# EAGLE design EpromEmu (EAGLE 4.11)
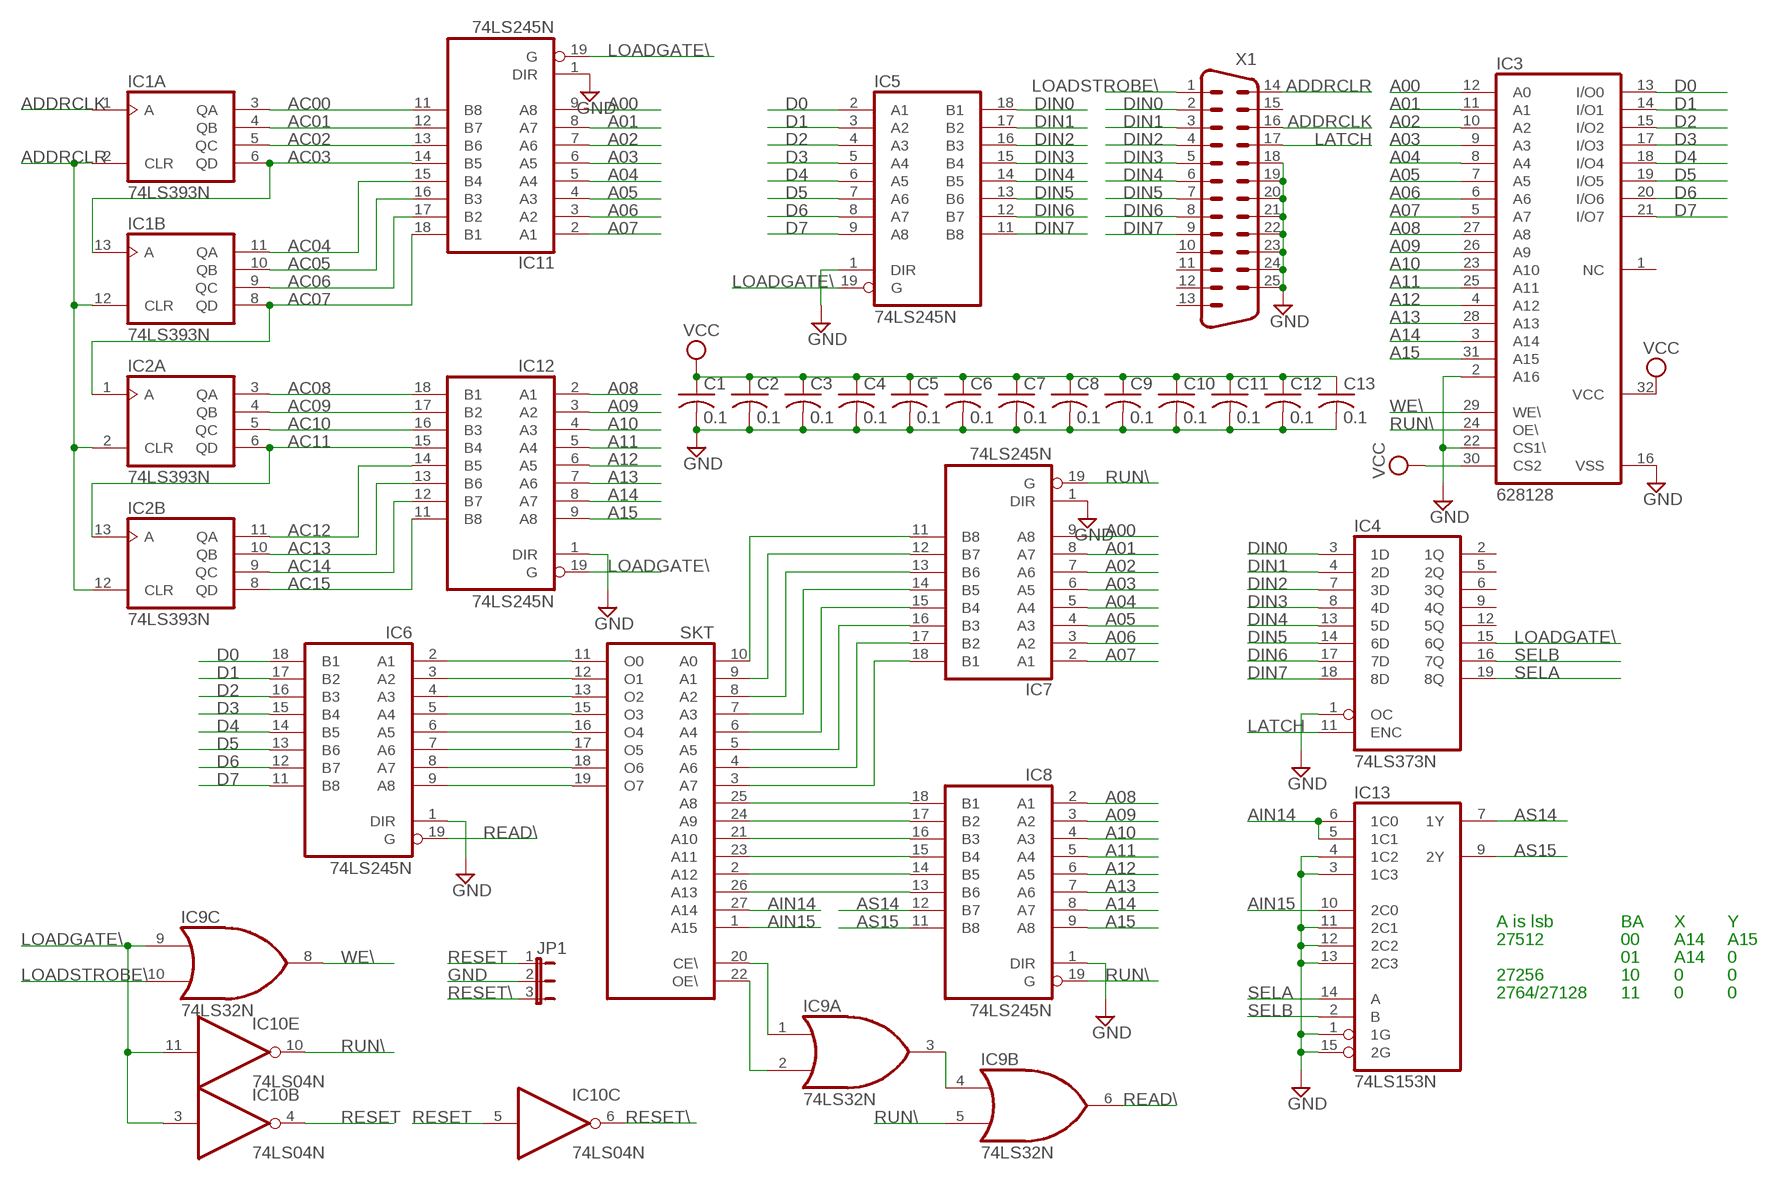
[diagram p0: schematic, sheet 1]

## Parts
C1  0.1  C-US050-025X075  [C050-025X075]
C2  0.1  C-US050-025X075  [C050-025X075]
C3  0.1  C-US050-025X075  [C050-025X075]
C4  0.1  C-US050-025X075  [C050-025X075]
C5  0.1  C-US050-025X075  [C050-025X075]
C6  0.1  C-US050-025X075  [C050-025X075]
C7  0.1  C-US050-025X075  [C050-025X075]
C8  0.1  C-US050-025X075  [C050-025X075]
C9  0.1  C-US050-025X075  [C050-025X075]
C10  0.1  C-US050-025X075  [C050-025X075]
C11  0.1  C-US050-025X075  [C050-025X075]
C12  0.1  C-US050-025X075  [C050-025X075]
C13  0.1  C-US050-025X075  [C050-025X075]
IC1  74LS393N  [DIL14]
IC2  74LS393N  [DIL14]
IC3  628128  628128P  [DIL32]
IC4  74LS373N  [DIL20]
IC5  74LS245N  [DIL20]
IC6  74LS245N  [DIL20]
IC7  74LS245N  [DIL20]
IC8  74LS245N  [DIL20]
IC9  74LS32N  [DIL14]
IC10  74LS04N  [DIL14]
IC11  74LS245N  [DIL20]
IC12  74LS245N  [DIL20]
IC13  74LS153N  [DIL16]
JP1  JP2E  [JP2]
SKT  27512  [DIL28]
X1  M25HP  [M25HP]

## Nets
A00: IC3.12(A0) IC7.9(A8) IC11.9(A8)
A01: IC3.11(A1) IC7.8(A7) IC11.8(A7)
A02: IC3.10(A2) IC7.7(A6) IC11.7(A6)
A03: IC3.9(A3) IC7.6(A5) IC11.6(A5)
A04: IC3.8(A4) IC7.5(A4) IC11.5(A4)
A05: IC3.7(A5) IC7.4(A3) IC11.4(A3)
A06: IC3.6(A6) IC7.3(A2) IC11.3(A2)
A07: IC3.5(A7) IC7.2(A1) IC11.2(A1)
A08: IC3.27(A8) IC8.2(A1) IC12.2(A1)
A09: IC3.26(A9) IC8.3(A2) IC12.3(A2)
A10: IC3.23(A10) IC8.4(A3) IC12.4(A3)
A11: IC3.25(A11) IC8.5(A4) IC12.5(A4)
A12: IC3.4(A12) IC8.6(A5) IC12.6(A5)
A13: IC3.28(A13) IC8.7(A6) IC12.7(A6)
A14: IC3.3(A14) IC8.8(A7) IC12.8(A7)
A15: IC3.31(A15) IC8.9(A8) IC12.9(A8)
AC00: IC1.3(A:QA) IC11.11(B8)
AC01: IC1.4(A:QB) IC11.12(B7)
AC02: IC1.5(A:QC) IC11.13(B6)
AC03: IC1.6(A:QD) IC1.13(B:A) IC11.14(B5)
AC04: IC1.11(B:QA) IC11.15(B4)
AC05: IC1.10(B:QB) IC11.16(B3)
AC06: IC1.9(B:QC) IC11.17(B2)
AC07: IC1.8(B:QD) IC2.1(A:A) IC11.18(B1)
AC08: IC2.3(A:QA) IC12.18(B1)
AC09: IC2.4(A:QB) IC12.17(B2)
AC10: IC2.5(A:QC) IC12.16(B3)
AC11: IC2.6(A:QD) IC2.13(B:A) IC12.15(B4)
AC12: IC2.11(B:QA) IC12.14(B5)
AC13: IC2.10(B:QB) IC12.13(B6)
AC14: IC2.9(B:QC) IC12.12(B7)
AC15: IC2.8(B:QD) IC12.11(B8)
ADDRCLK: IC1.1(A:A) X1.16
ADDRCLR: IC1.2(A:CLR) IC1.12(B:CLR) IC2.2(A:CLR) IC2.12(B:CLR) X1.14
AIN14: IC13.5(1C1) IC13.6(1C0) SKT.27(A14)
AIN15: IC13.10(2C0) SKT.1(A15)
AS14: IC8.12(B7) IC13.7(1Y)
AS15: IC8.11(B8) IC13.9(2Y)
D0: IC3.13(I/O0) IC5.2(A1) IC6.18(B1)
D1: IC3.14(I/O1) IC5.3(A2) IC6.17(B2)
D2: IC3.15(I/O2) IC5.4(A3) IC6.16(B3)
D3: IC3.17(I/O3) IC5.5(A4) IC6.15(B4)
D4: IC3.18(I/O4) IC5.6(A5) IC6.14(B5)
D5: IC3.19(I/O5) IC5.7(A6) IC6.13(B6)
D6: IC3.20(I/O6) IC5.8(A7) IC6.12(B7)
D7: IC3.21(I/O7) IC5.9(A8) IC6.11(B8)
DIN0: IC4.3(1D) IC5.18(B1) X1.2
DIN1: IC4.4(2D) IC5.17(B2) X1.3
DIN2: IC4.7(3D) IC5.16(B3) X1.4
DIN3: IC4.8(4D) IC5.15(B4) X1.5
DIN4: IC4.13(5D) IC5.14(B5) X1.6
DIN5: IC4.14(6D) IC5.13(B6) X1.7
DIN6: IC4.17(7D) IC5.12(B7) X1.8
DIN7: IC4.18(8D) IC5.11(B8) X1.9
GND: C1.2 C2.2 C3.2 C4.2 C5.2 C6.2 C7.2 C8.2 C9.2 C10.2 C11.2 C12.2 C13.2 IC3.2(A16) IC3.16(VSS) IC3.22(CS1\) IC4.1(OC) IC5.1(DIR) IC6.1(DIR) IC7.1(DIR) IC8.1(DIR) IC11.1(DIR) IC12.1(DIR) IC13.1(1G) IC13.3(1C3) IC13.4(1C2) IC13.11(2C1) IC13.12(2C2) IC13.13(2C3) IC13.15(2G) JP1.2 X1.18 X1.19 X1.20 X1.21 X1.22 X1.23 X1.24 X1.25
LATCH: IC4.11(ENC) X1.17
LOADGATE\: IC4.15(6Q) IC5.19(G) IC9.9(C:I0) IC10.3(B:I) IC10.11(E:I) IC11.19(G) IC12.19(G)
LOADSTROBE\: IC9.10(C:I1) X1.1
N$1: IC6.2(A1) SKT.11(O0)
N$2: IC6.3(A2) SKT.12(O1)
N$3: IC6.4(A3) SKT.13(O2)
N$4: IC6.5(A4) SKT.15(O3)
N$5: IC6.6(A5) SKT.16(O4)
N$6: IC6.7(A6) SKT.17(O5)
N$7: IC6.8(A7) SKT.18(O6)
N$8: IC6.9(A8) SKT.19(O7)
N$9: IC9.2(A:I1) SKT.22(OE\)
N$10: IC9.1(A:I0) SKT.20(CE\)
N$11: IC8.13(B6) SKT.26(A13)
N$12: IC8.14(B5) SKT.2(A12)
N$13: IC8.15(B4) SKT.23(A11)
N$14: IC8.16(B3) SKT.21(A10)
N$15: IC8.17(B2) SKT.24(A9)
N$16: IC8.18(B1) SKT.25(A8)
N$17: IC7.18(B1) SKT.3(A7)
N$18: IC7.17(B2) SKT.4(A6)
N$19: IC7.16(B3) SKT.5(A5)
N$20: IC7.15(B4) SKT.6(A4)
N$21: IC7.14(B5) SKT.7(A3)
N$22: IC7.13(B6) SKT.8(A2)
N$23: IC7.12(B7) SKT.9(A1)
N$24: IC7.11(B8) SKT.10(A0)
N$25: IC9.3(A:O) IC9.4(B:I0)
READ\: IC6.19(G) IC9.6(B:O)
RESET: IC10.4(B:O) IC10.5(C:I) JP1.1
RESET\: IC10.6(C:O) JP1.3
RUN\: IC3.24(OE\) IC7.19(G) IC8.19(G) IC9.5(B:I1) IC10.10(E:O)
SELA: IC4.19(8Q) IC13.14(A)
SELB: IC4.16(7Q) IC13.2(B)
VCC [power]: C1.1 C2.1 C3.1 C4.1 C5.1 C6.1 C7.1 C8.1 C9.1 C10.1 C11.1 C12.1 C13.1 IC3.30(CS2) IC3.32(VCC)
WE\: IC3.29(WE\) IC9.8(C:O)
Unconnected: IC3.1(NC) IC4.2(1Q) IC4.5(2Q) IC4.6(3Q) IC4.9(4Q) IC4.12(5Q) IC9.11(D:O) IC9.12(D:I0) IC9.13(D:I1) IC10.1(A:I) IC10.2(A:O) IC10.8(D:O) IC10.9(D:I) IC10.12(F:O) IC10.13(F:I) X1.10 X1.11 X1.12 X1.13 X1.15 X1.G1 X1.G2

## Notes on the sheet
- A is lsb | BA | X | Y
- 27512 | 00 | A14 | A15
- 01 | A14 | 0
- 27256 | 10 | 0 | 0
- 2764/27128 | 11 | 0 | 0

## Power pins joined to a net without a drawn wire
GND: IC1.7(P:GND) IC2.7(P:GND) IC4.10(GND) IC5.10(GND) IC6.10(GND) IC7.10(GND) IC8.10(GND) IC9.7(P:GND) IC10.7(P:GND) IC11.10(GND) IC12.10(GND) IC13.8(GND) SKT.14(GND)
VCC: IC1.14(P:VCC) IC2.14(P:VCC) IC4.20(VCC) IC5.20(VCC) IC6.20(VCC) IC7.20(VCC) IC8.20(VCC) IC9.14(P:VCC) IC10.14(P:VCC) IC11.20(VCC) IC12.20(VCC) IC13.16(VCC) SKT.28(VCC)

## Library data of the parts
C1-C13 = rcl:C-US: CAPACITOR, American symbol
IC1 IC2 = 74xx-us:74*393: Dual 4-bit decade and binary COUNTER
IC3 = memory-hitachi:628128P: MEMORY
IC4 = 74xx-us:74*373: Octal D type transparent LATCH, edge triggered
IC5-IC8 IC11 IC12 = 74xx-us:74*245: Octal BUS TRANSCEIVER, 3-state
IC9 = 74xx-us:74*32: Quad 2-input OR gate
IC10 = 74xx-us:74*04: Hex INVERTER
IC13 = 74xx-us:74*153: Dual 4-line to 1-line data SELECTOR/MULTIPLEXER
JP1 = jumper:JP2E: JUMPER
SKT = memory:27512: MEMORY
X1 = con-subd:M25HP: SUB-D

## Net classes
1 power: width 0.508 mm, drill 0.127 mm

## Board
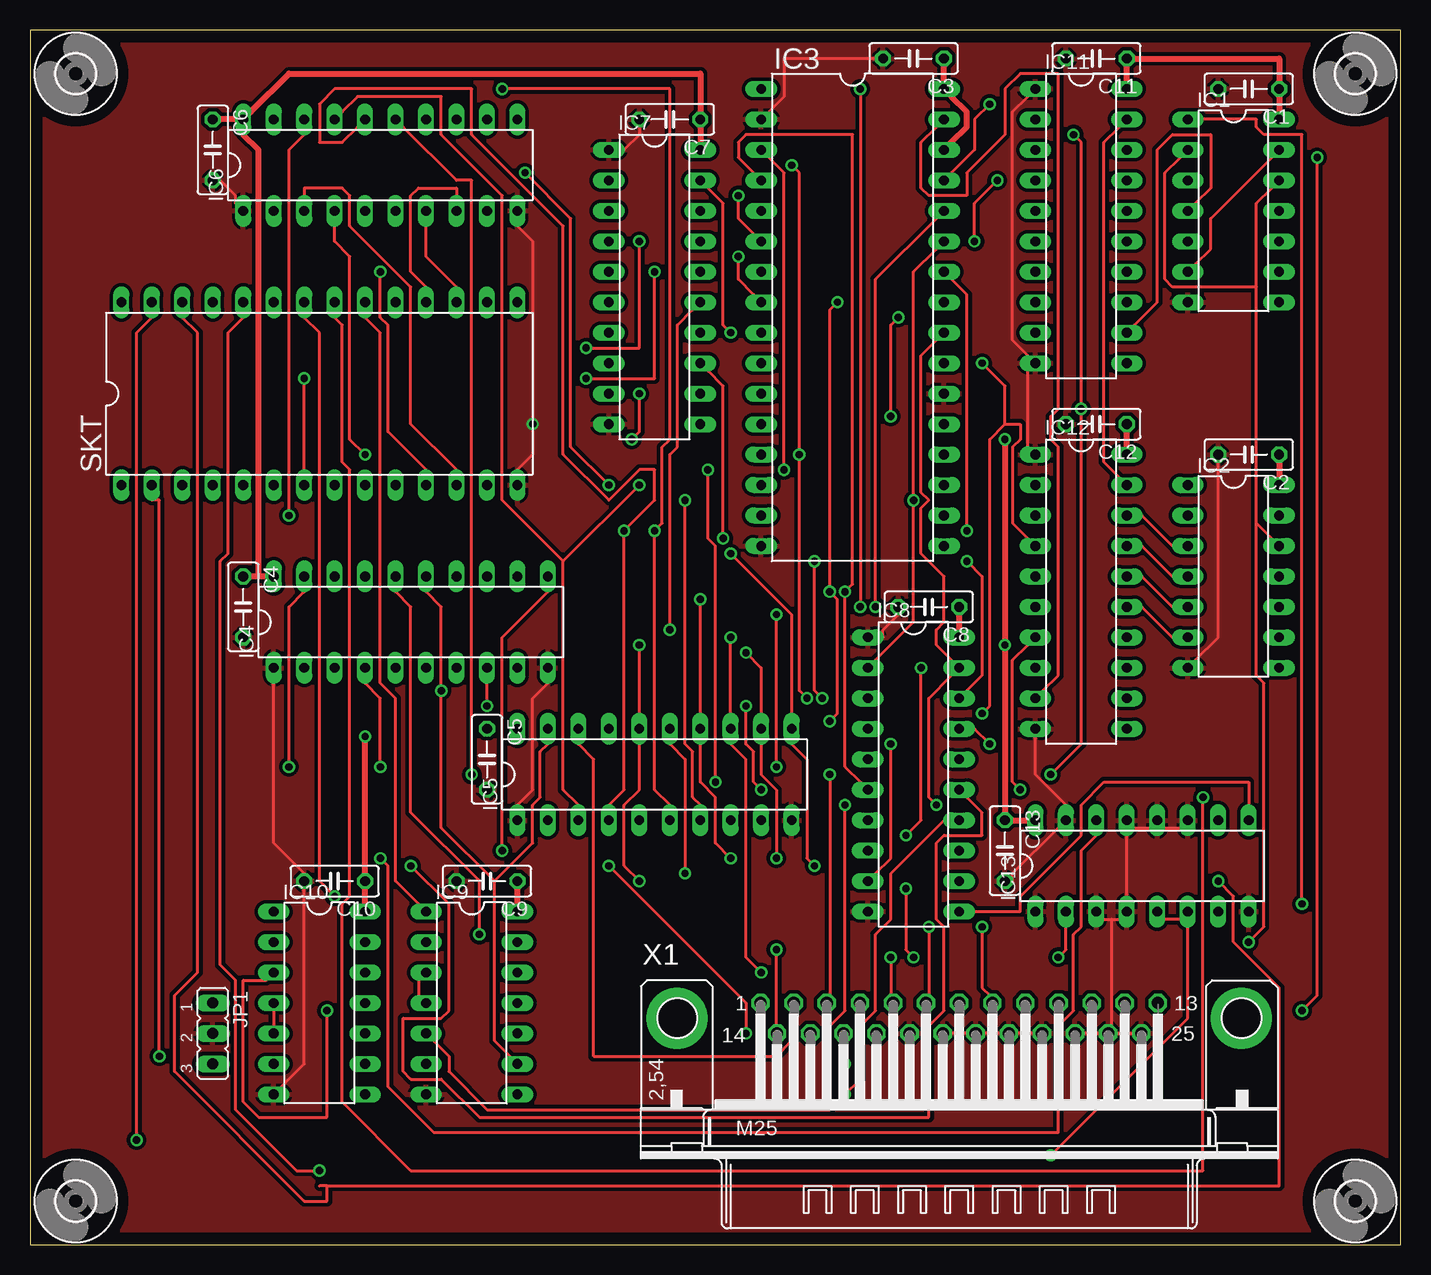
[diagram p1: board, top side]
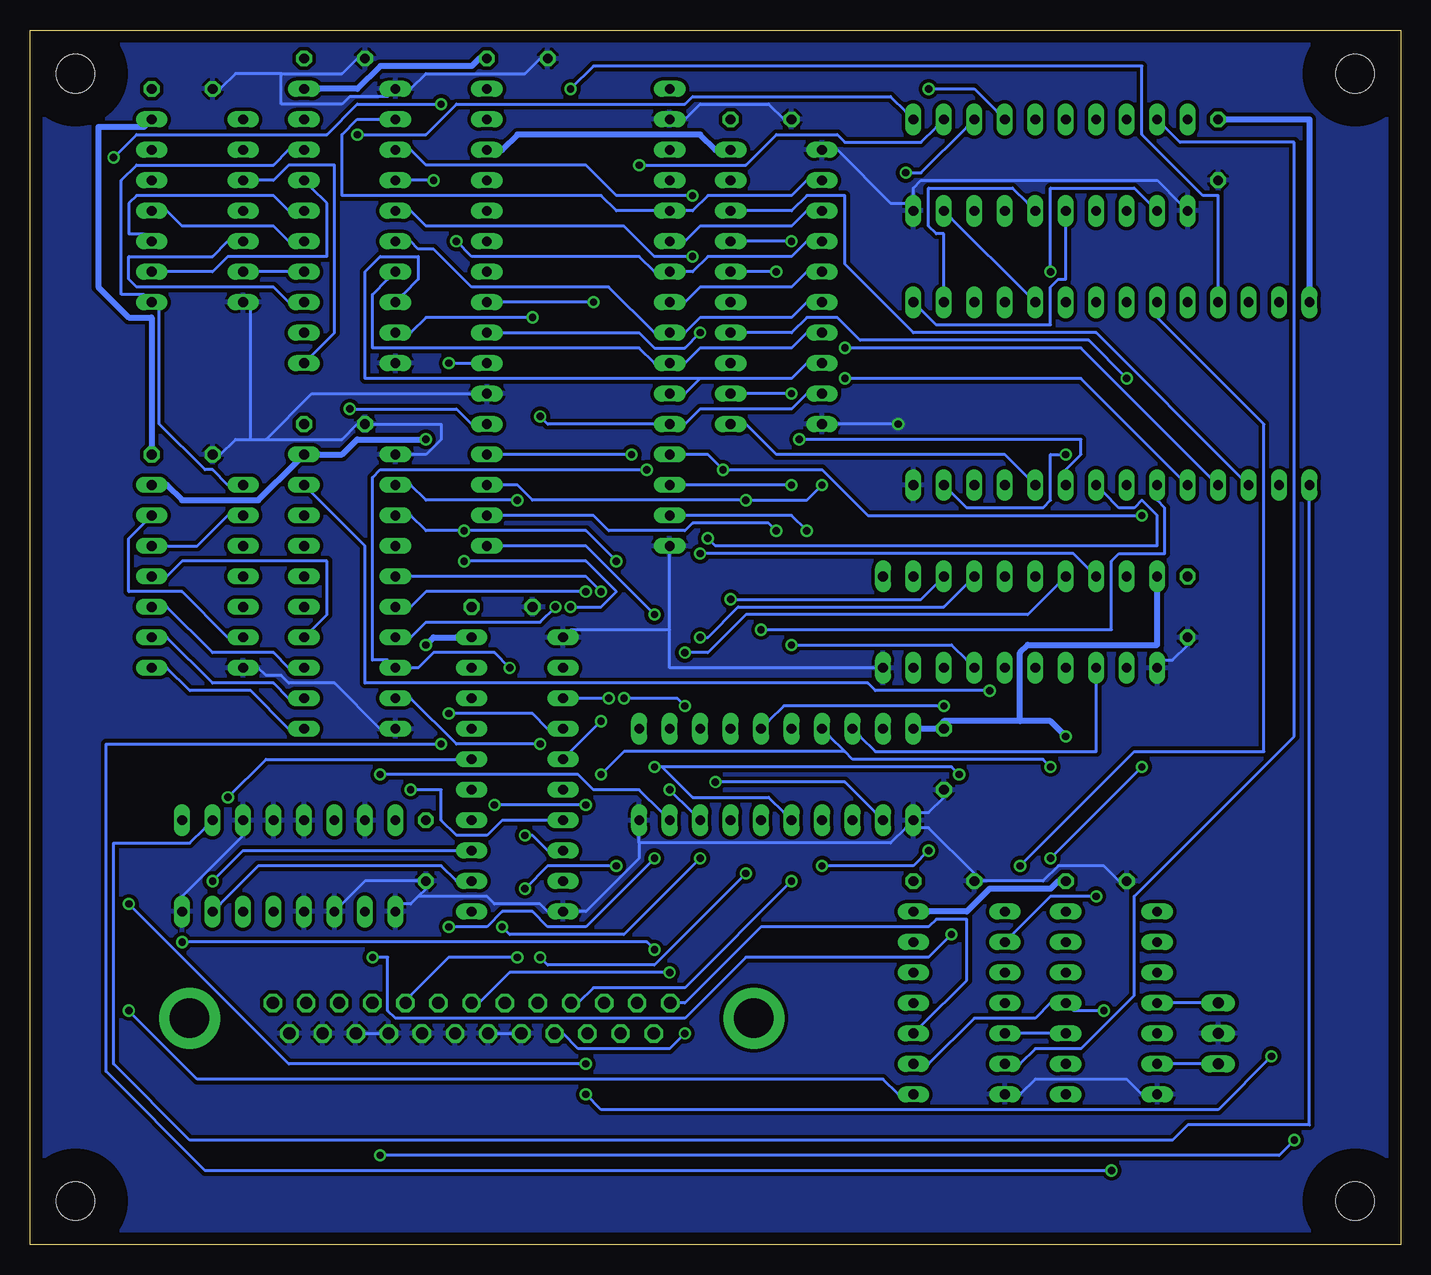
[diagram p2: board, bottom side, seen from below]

Size 114.28 x 101.27 mm. Coordinates in mm from the lower left corner, seen from the top.
Outline: 0,0 114.28,0 114.28,101.27 0,101.27 0,0
Copper layers (1*16): Top 0.035mm / dielectric 1.5mm / Bottom 0.035mm
Design rules "default": minimum track width 10mil, minimum drill 24mil, track to track 8mil, track to pad 8mil, pad to pad 8mil, via to via 8mil, smd to smd 8mil, copper to edge 40mil, drill to drill 8mil, minimum pad ring 10mil, minimum via ring 8mil, stop-mask expansion 4mil, vias tented up to drill 0mil, thermal gap 10mil

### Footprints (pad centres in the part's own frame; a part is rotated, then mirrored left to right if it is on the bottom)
C050-025X075 = drill 0.813 octagon: 1 -2.54,0; 2 2.54,0
DIL14 = drill 0.813 long: 1 -7.62,-3.81; 2 -5.08,-3.81; 3 -2.54,-3.81; 4 0,-3.81; 5 2.54,-3.81; 6 5.08,-3.81; 7 7.62,-3.81; 8 7.62,3.81; 9 5.08,3.81; 10 2.54,3.81; 11 0,3.81; 12 -2.54,3.81; 13 -5.08,3.81; 14 -7.62,3.81
DIL32 = drill 0.813 long: 1 -19.05,-7.62; 2 -16.51,-7.62; 3 -13.97,-7.62; 4 -11.43,-7.62; 5 -8.89,-7.62; 6 -6.35,-7.62; 7 -3.81,-7.62; 8 -1.27,-7.62; 9 1.27,-7.62; 10 3.81,-7.62; 11 6.35,-7.62; 12 8.89,-7.62; 13 11.43,-7.62; 14 13.97,-7.62; 15 16.51,-7.62; 16 19.05,-7.62; 17 19.05,7.62; 18 16.51,7.62; 19 13.97,7.62; 20 11.43,7.62; 21 8.89,7.62; 22 6.35,7.62; 23 3.81,7.62; 24 1.27,7.62; 25 -1.27,7.62; 26 -3.81,7.62; 27 -6.35,7.62; 28 -8.89,7.62; 29 -11.43,7.62; 30 -13.97,7.62; 31 -16.51,7.62; 32 -19.05,7.62
DIL20 = drill 0.813 long: 1 -11.43,-3.81; 2 -8.89,-3.81; 3 -6.35,-3.81; 4 -3.81,-3.81; 5 -1.27,-3.81; 6 1.27,-3.81; 7 3.81,-3.81; 8 6.35,-3.81; 9 8.89,-3.81; 10 11.43,-3.81; 11 11.43,3.81; 12 8.89,3.81; 13 6.35,3.81; 14 3.81,3.81; 15 1.27,3.81; 16 -1.27,3.81; 17 -3.81,3.81; 18 -6.35,3.81; 19 -8.89,3.81; 20 -11.43,3.81
DIL16 = drill 0.813 long: 1 -8.89,-3.81; 2 -6.35,-3.81; 3 -3.81,-3.81; 4 -1.27,-3.81; 5 1.27,-3.81; 6 3.81,-3.81; 7 6.35,-3.81; 8 8.89,-3.81; 9 8.89,3.81; 10 6.35,3.81; 11 3.81,3.81; 12 1.27,3.81; 13 -1.27,3.81; 14 -3.81,3.81; 15 -6.35,3.81; 16 -8.89,3.81
JP2 = drill 0.914 long: 1 -2.54,0; 2 0,0; 3 2.54,0
DIL28 = drill 0.813 long: 1 -16.51,-7.62; 2 -13.97,-7.62; 3 -11.43,-7.62; 4 -8.89,-7.62; 5 -6.35,-7.62; 6 -3.81,-7.62; 7 -1.27,-7.62; 8 1.27,-7.62; 9 3.81,-7.62; 10 6.35,-7.62; 11 8.89,-7.62; 12 11.43,-7.62; 13 13.97,-7.62; 14 16.51,-7.62; 15 16.51,7.62; 16 13.97,7.62; 17 11.43,7.62; 18 8.89,7.62; 19 6.35,7.62; 20 3.81,7.62; 21 1.27,7.62; 22 -1.27,7.62; 23 -3.81,7.62; 24 -6.35,7.62; 25 -8.89,7.62; 26 -11.43,7.62; 27 -13.97,7.62; 28 -16.51,7.62
3,2 = hole 3.2: 0,0
M25HP = drill 1.016 octagon: 1 -16.561,1.27; 2 -13.792,1.27; 3 -11.049,1.27; 4 -8.28,1.27; 5 -5.512,1.27; 6 -2.769,1.27; 7 0,1.27; 8 2.769,1.27; 9 5.512,1.27; 10 8.28,1.27; 11 11.049,1.27; 12 13.792,1.27; 13 16.561,1.27; 14 -15.189,-1.27; 15 -12.421,-1.27; 16 -9.652,-1.27; 17 -6.909,-1.27; 18 -4.14,-1.27; 19 -1.372,-1.27; 20 1.372,-1.27; 21 4.14,-1.27; 22 6.909,-1.27; 23 9.652,-1.27; 24 12.421,-1.27; 25 15.189,-1.27 | drill 3.302 pad 5.08 round: G1 -23.52,0; G2 23.52,0

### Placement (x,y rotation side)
C1  101.59,96.35 180 top
C2  101.59,65.88 180 top
C3  73.66,98.89 180 top
C4  17.78,53.18 270 top
C5  38.09,40.48 270 top
C6  15.23,91.27 270 top
C7  53.34,93.81 180 top
C8  74.93,53.18 180 top
C9  38.09,30.32 180 top
C10  25.39,30.32 180 top
C11  88.9,98.89 180 top
C12  88.9,68.41 180 top
C13  81.28,32.86 270 top
IC1  100.33,86.19 270 top
IC2  100.33,55.72 270 top
IC3  68.58,77.3 270 top
IC4  31.75,51.91 0 top
IC5  52.06,39.2 0 top
IC6  29.21,90 0 top
IC7  52.06,79.84 270 top
IC8  73.66,39.2 270 top
IC9  36.82,20.16 270 top
IC10  24.12,20.16 270 top
IC11  87.62,84.92 270 top
IC12  87.62,54.45 270 top
IC13  92.7,31.59 0 top
JP1  15.23,17.62 270 top
SKT  24.12,70.95 0 top
U$1  [3,2]  3.81,97.62 0 top
U$2  [3,2]  3.81,3.65 0 top
U$3  [3,2]  110.48,3.65 0 top
U$4  [3,2]  110.48,97.62 0 top
X1  77.47,18.89 0 top

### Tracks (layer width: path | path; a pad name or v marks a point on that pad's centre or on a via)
A00  (via drill 0.61)
  Top 0.254: v72.39,77.3 71.75,76.67 v71.75,69.05
  Bottom 0.254: IC7.9 49.52,70.95 50.79,69.68 58.41,69.68 59.68,68.41 IC3.12 62.22,68.41 71.12,68.41 v71.75,69.05 | v72.39,77.3 81.28,77.3 82.55,76.03 IC11.9
A01
  Bottom 0.254: 58.41,72.22 50.79,72.22 49.52,73.49 IC7.8 | 58.41,72.22 59.68,70.95 IC3.11 | 58.41,72.22 86.36,72.22 86.36,81.11 85.09,82.38 81.91,82.38 81.91,80.48 83.18,79.21 IC11.8
A02
  Bottom 0.254: IC7.7 49.52,76.03 50.79,74.77 58.41,74.77 59.68,73.49 IC3.10 62.22,73.49 63.49,74.77 85.72,74.77 85.72,79.21 84.45,80.48 IC11.7
A03
  Bottom 0.254: IC7.6 49.52,78.57 50.79,77.3 58.41,77.3 59.68,76.03 IC3.9 62.22,76.03 66.04,79.84 77.47,79.84 80.64,83.02 81.91,83.02 82.55,83.65 IC11.6
A04  (via drill 0.61)
  Top 0.254: v59.05,82.38 59.05,80.48 60.32,79.21 IC3.8
  Bottom 0.254: IC7.5 49.52,81.11 50.79,79.84 58.41,79.84 59.68,78.57 IC3.8 | v59.05,82.38 62.22,82.38 64.77,84.92 81.28,84.92 82.55,86.19 IC11.5
A05  (via drill 0.61)
  Top 0.254: v80.64,88.73 78.73,86.83 v78.73,83.65
  Bottom 0.254: IC7.4 49.52,83.65 50.79,82.38 57.78,82.38 59.05,81.11 59.68,81.11 IC3.7 62.22,81.11 63.49,82.38 77.47,82.38 v78.73,83.65 | v80.64,88.73 82.55,88.73 IC11.4
A06  (via drill 0.61)
  Top 0.254: v59.05,87.46 59.05,85.56 60.32,84.29 IC3.6
  Bottom 0.254: IC7.3 49.52,86.19 50.79,84.92 58.41,84.92 59.68,83.65 IC3.6 | v59.05,87.46 65.4,87.46 67.94,90 81.28,90 82.55,91.27 IC11.3
A07
  Bottom 0.254: IC7.2 49.52,88.73 50.79,87.46 57.78,87.46 59.05,86.19 59.68,86.19 IC3.5 62.22,86.19 65.4,86.19 66.67,87.46 88.26,87.46 88.26,92.54 86.99,93.81 85.09,93.81 IC11.2
A08  (via drill 0.61)
  Top 0.254: IC8.2 70.48,48.73 73.66,51.91 v73.66,62.06 73.66,81.11 75.56,83.02 IC3.27
  Bottom 0.254: v73.66,62.06 81.28,62.06 82.55,63.34 IC12.2
A09  (via drill 0.61)
  Top 0.254: v66.04,45.55 65.4,46.19 v65.4,56.98 | v78.1,59.52 78.1,79.21 76.83,80.48 IC3.26
  Bottom 0.254: v66.04,45.55 68.58,45.55 IC8.3 | v65.4,56.98 67.94,59.52 v78.1,59.52 81.28,59.52 82.55,60.8 IC12.3
A10  (via drill 0.61)
  Top 0.254: v79.37,44.29 80.01,44.92 80.01,67.14 81.28,68.41 | 81.28,68.41 82.55,68.41 82.55,67.14 81.91,66.51 81.91,60.16 83.18,58.89 IC12.4 | v79.37,73.49 81.28,71.59 81.28,68.41
  Bottom 0.254: v79.37,44.29 72.39,44.29 71.12,43.02 IC8.4 | v79.37,73.49 77.47,73.49 IC3.23
A11  (via drill 0.61)
  Top 0.254: v66.67,43.65 67.31,44.29 67.31,53.81 v66.67,54.45 66.67,77.94 v67.31,78.57
  Bottom 0.254: v66.67,43.65 69.21,41.11 IC8.5 | v66.67,54.45 67.94,55.72 82.55,55.72 IC12.5 | v67.31,78.57 74.93,78.57 IC3.25
A12  (via drill 0.61)
  Top 0.254: IC8.6 69.21,38.57 67.94,39.84 v67.94,54.45 68.58,55.08 68.58,92.54 59.68,92.54 59.05,91.91 59.05,90.64 60.32,89.37 IC3.4
  Bottom 0.254: v67.94,54.45 81.28,54.45 82.55,53.18 IC12.6
A13  (via drill 0.61)
  Top 0.254: v82.55,37.94 81.91,38.57 81.91,48.73 83.18,50 IC12.7 | v70.48,53.18 70.48,80.48 75.56,85.56 IC3.28
  Bottom 0.254: v82.55,37.94 80.01,37.94 80.01,35.4 78.73,34.12 76.2,34.12 74.93,35.4 71.12,35.4 IC8.7 | v70.48,53.18 71.75,51.91 81.28,51.91 82.55,50.63 IC12.7
A14  (via drill 0.61)
  Top 0.254: v73.02,34.12 74.29,35.4 v74.29,48.09 | v62.86,64.6 62.86,89.37 61.59,90.64 IC3.3
  Bottom 0.254: v73.02,34.12 72.39,34.12 71.12,32.86 IC8.8 | v74.29,48.09 75.56,49.37 80.64,49.37 81.91,48.09 82.55,48.09 IC12.8 84.45,48.73 85.72,48.73 85.72,63.97 85.09,64.6 v62.86,64.6
A15  (via drill 0.61)
  Top 0.254: v71.75,41.74 71.75,32.22 70.48,30.95 IC8.9 | IC3.31 75.56,93.18 74.29,91.91 74.29,88.1 74.93,87.46 78.1,87.46 78.1,89.37 81.28,92.54 81.28,96.35 82.55,97.62 85.72,97.62 85.72,69.68 85.09,69.05 85.09,67.14 85.72,66.51 85.72,47.46 84.45,46.19 IC12.9
  Bottom 0.254: v71.75,41.74 78.73,41.74 82.55,45.55 IC12.9
AC00
  Bottom 0.254: IC11.11 90.8,74.13 88.9,76.03 88.9,90 92.7,90 93.98,88.73 95.25,88.73 IC1.3
AC01
  Top 0.254: IC11.12 92.07,76.67 93.98,78.57 93.98,91.27 95.25,92.54 98.42,92.54 98.42,88.1 97.15,86.83 IC1.4
AC02
  Bottom 0.254: IC11.13 92.7,78.57 93.98,79.84 105.41,79.84 106.04,80.48 106.04,82.38 99.06,82.38 97.79,83.65 IC1.5
AC03
  Top 0.254: IC1.13 103.5,90.64 98.42,85.56 98.42,83.02 97.15,81.75 IC1.6
  Bottom 0.254: IC11.14 92.7,81.11 95.25,81.11 IC1.6
AC04
  Bottom 0.254: IC11.15 92.7,83.65 93.98,84.92 101.59,84.92 102.87,86.19 IC1.11
AC05
  Bottom 0.254: IC11.16 92.7,86.19 93.98,87.46 105.41,87.46 106.04,86.83 106.04,84.29 104.77,84.29 IC1.10
AC06
  Bottom 0.254: IC11.17 90.8,88.1 89.53,86.83 89.53,82.38 97.79,82.38 99.06,81.11 102.87,81.11 IC1.9
AC07
  Bottom 0.254: IC2.1 97.79,63.34 99.06,64.6 99.69,64.6 103.5,68.41 103.5,77.94 IC1.8 104.77,79.21 106.68,79.21 106.68,88.73 105.41,90 93.98,90 92.7,91.27 IC11.18
AC08
  Top 0.254: IC12.18 92.7,60.8 95.25,58.26 IC2.3
AC09
  Top 0.254: IC12.17 92.7,58.26 95.25,55.72 IC2.4
AC10
  Top 0.254: IC12.16 92.7,55.72 95.25,53.18 IC2.5
AC11
  Top 0.254: IC12.15 92.7,53.18 95.25,50.63 IC2.6
  Bottom 0.254: IC2.13 104.77,60.16 106.04,58.89 106.04,54.45 101.59,54.45 97.79,50.63 IC2.6
AC12
  Bottom 0.254: IC12.14 90.8,51.27 89.53,52.54 89.53,56.98 101.59,56.98 102.87,55.72 IC2.11
AC13
  Bottom 0.254: IC12.13 92.7,48.09 93.98,49.37 99.06,49.37 102.87,53.18 IC2.10
AC14
  Bottom 0.254: IC12.12 92.7,45.55 93.98,46.83 99.06,46.83 102.87,50.63 IC2.9
AC15
  Bottom 0.254: IC12.11 92.7,43.02 95.88,46.19 100.96,46.19 102.87,48.09 IC2.8
ADDRCLK  (via drill 0.61)
  Top 0.254: v106.04,28.41 106.04,92.54 102.87,92.54 102.23,93.18 102.23,93.81 97.79,93.81 IC1.1 | v67.94,15.08 67.94,16.98 X1.16
  Bottom 0.254: v106.04,28.41 92.7,15.08 v67.94,15.08
ADDRCLR  (via drill 0.61)
  Top 0.254: 102.23,60.16 102.23,79.84 | 102.23,79.84 102.23,86.83 103.5,88.1 IC1.12 | 102.23,60.16 103.5,58.89 IC2.12 | 102.23,79.84 95.25,79.84 94.61,80.48 94.61,89.37 95.88,90.64 IC1.2 | v62.22,24.6 62.22,18.25 X1.14 | v101.59,25.23 102.87,26.51 102.87,46.83 102.23,47.46 102.23,60.16
  Bottom 0.254: IC2.2 97.79,60.8 100.33,58.26 102.87,58.26 IC2.12 | v62.22,24.6 62.86,25.23 v101.59,25.23
AIN14  (via drill 0.61)
  Top 0.254: IC13.5 94.61,27.14 95.88,27.14 IC13.6 96.52,26.51 96.52,18.89 v85.09,7.46 | v8.88,8.73 8.88,76.03 10.15,77.3 SKT.27
  Bottom 0.254: v8.88,8.73 10.15,7.46 v85.09,7.46
AIN15
  Bottom 0.254: SKT.1 7.62,62.06 7.62,10 17.78,10 19.05,8.73 100.96,8.73 107.31,15.08 107.31,33.49 100.96,33.49 99.69,34.76 IC13.10
AS14
  Bottom 0.254: IC8.12 78.73,30.32 80.01,31.59 95.25,31.59 98.42,28.41 IC13.7
AS15
  Top 0.254: IC8.11 78.73,27.78 82.55,27.78 82.55,29.05 87.62,34.12 87.62,36.66 89.53,38.57 101.59,38.57 101.59,36.66 IC13.9
D0  (via drill 0.61)
  Top 0.254: v57.14,38.57 57.14,58.26 56.51,58.89 v56.51,64.6 | v21.59,60.8 21.59,91.27 22.86,92.54 IC6.18
  Bottom 0.254: v57.14,38.57 46.35,38.57 43.81,36.03 IC5.2 | IC3.13 59.68,65.88 57.78,65.88 v56.51,64.6 48.25,64.6 44.45,60.8 v21.59,60.8
D1  (via drill 0.61)
  Top 0.254: 44.45,56.98 44.45,37.94 45.71,36.66 IC5.3 | 44.45,56.98 v50.79,63.34 | 44.45,56.98 39.36,62.06 39.36,87.46 34.28,92.54 34.28,95.72 27.3,95.72 26.03,94.45 IC6.17
  Bottom 0.254: v50.79,63.34 59.68,63.34 IC3.14
D2  (via drill 0.61)
  Top 0.254: IC5.4 48.25,36.66 49.52,37.94 v49.52,59.52 52.06,62.06 52.06,64.6 50.79,64.6 48.25,62.06 44.45,65.88 44.45,84.92 36.82,92.54 36.82,96.35 25.39,96.35 24.12,95.08 24.12,91.91 26.03,91.91 27.3,93.18 IC6.16
  Bottom 0.254: v49.52,59.52 50.79,60.8 59.68,60.8 IC3.15
D3  (via drill 0.61)
  Top 0.254: v62.22,39.84 v62.22,52.54 | v36.82,39.2 36.82,88.73 35.55,88.73 31.11,93.18 IC6.15
  Bottom 0.254: 61.59,39.84 59.05,37.3 52.7,37.3 51.43,36.03 IC5.5 | 61.59,39.84 v62.22,39.84 | v62.22,52.54 67.94,58.26 74.93,58.26 IC3.17 | v36.82,39.2 37.46,39.84 61.59,39.84
D4  (via drill 0.61)
  Top 0.254: IC5.6 53.34,36.66 52.06,37.94 v52.06,59.52 52.7,60.16 52.7,66.51 53.34,67.14 53.34,96.35 v39.36,96.35
  Bottom 0.254: v52.06,59.52 52.7,60.16 59.05,60.16 59.68,59.52 66.04,59.52 67.31,60.8 74.93,60.8 IC3.18 | v39.36,96.35 35.55,96.35 33.65,94.45 IC6.14
D5  (via drill 0.61)
  Top 0.254: v54.6,62.06 54.6,41.74 55.24,41.11 55.24,37.3 55.88,36.66 IC5.7 | v41.27,89.37 45.08,85.56 45.08,66.51 v48.25,63.34
  Bottom 0.254: IC3.19 74.93,63.34 73.66,63.34 72.39,62.06 v54.6,62.06 49.52,62.06 v48.25,63.34 | v41.27,89.37 40,89.37 36.19,93.18 IC6.13
D6  (via drill 0.61)
  Top 0.254: v60.95,37.94 60.32,38.57 60.32,41.11 59.68,41.74 v59.68,44.92 | v64.77,45.55 64.13,46.19 v64.13,65.88 64.13,89.37 v63.49,90
  Bottom 0.254: v60.95,37.94 59.05,36.03 IC5.8 | v59.68,44.92 60.32,45.55 v64.77,45.55 | v64.13,65.88 74.93,65.88 IC3.20 | v63.49,90 54.6,90 52.06,92.54 46.98,92.54 46.35,91.91 40,91.91 38.73,93.18 IC6.12
D7  (via drill 0.61)
  Top 0.254: v85.09,39.2 87.62,41.74 v87.62,69.68 87.62,91.91 v86.99,92.54
  Bottom 0.254: v85.09,39.2 68.58,39.2 67.31,37.94 63.49,37.94 61.59,36.03 IC5.9 | v87.62,69.68 78.73,69.68 77.47,68.41 IC3.21 | v86.99,92.54 81.28,92.54 78.73,95.08 59.68,95.08 59.05,95.72 42.54,95.72 41.27,94.45 IC6.11
DIN0
  Top 0.254: X1.2 63.49,19.52 63.49,16.98 62.22,15.71 46.98,15.71 46.98,40.48 45.71,41.74 IC5.18
  Bottom 0.254: IC4.3 25.39,46.83 25.39,41.11 43.81,41.11 45.08,42.38 IC5.18
DIN1  (via drill 0.61)
  Top 0.254: v29.21,39.84 29.21,45.55 27.94,46.83 IC4.4 | v66.67,39.2 66.67,20.79 X1.3
  Bottom 0.254: v29.21,39.84 29.84,40.48 45.71,40.48 46.35,41.11 | 46.35,41.11 47.62,42.38 IC5.17 | v66.67,39.2 64.77,41.11 46.35,41.11
DIN2  (via drill 0.61)
  Top 0.254: v50.79,50 50.79,44.29 IC5.16 50.79,41.74 50.79,37.94 49.52,36.66 49.52,31.59 v50.79,30.32
  Bottom 0.254: v50.79,50 37.46,50 36.19,48.73 IC4.7 | v50.79,30.32 59.68,21.43 67.31,21.43 68.58,20.16 X1.4
DIN3  (via drill 0.61)
  Top 0.254: v38.09,44.92 38.09,46.83 IC4.8 | v71.75,23.96 71.75,20.79 X1.5 | v54.6,30.95 54.6,40.48 53.34,41.74 IC5.15
  Bottom 0.254: v38.09,44.92 51.43,44.92 52.7,43.65 IC5.15 | v71.75,23.96 71.12,23.33 62.22,23.33 v54.6,30.95
DIN4  (via drill 0.61)
  Top 0.254: v55.88,53.81 55.88,44.29 IC5.14 55.88,41.74 55.88,38.57 57.14,37.3 57.14,33.49 v58.41,32.22 | v74.93,26.51 74.93,20.79 X1.6
  Bottom 0.254: v55.88,53.81 40,53.81 38.73,55.08 IC4.13 | v74.93,26.51 74.29,25.87 64.77,25.87 v58.41,32.22
DIN5  (via drill 0.61)
  Top 0.254: v58.41,50.63 58.41,44.29 IC5.13 58.41,41.74 59.68,40.48 59.68,23.96 v60.95,22.7
  Bottom 0.254: v58.41,50.63 57.78,50.63 55.24,53.18 38.09,53.18 36.19,55.08 IC4.14 | v60.95,22.7 74.29,22.7 76.83,20.16 X1.7
DIN6  (via drill 0.61)
  Top 0.254: v59.68,49.37 60.95,48.09 60.95,44.29 IC5.12 60.95,41.74 60.95,39.2 62.22,37.94 v62.22,32.22 | v79.37,26.51 79.37,21.43 80.01,20.79 X1.8
  Bottom 0.254: v59.68,49.37 57.78,49.37 54.6,52.54 31.11,52.54 28.57,55.08 IC4.17 | v79.37,26.51 76.2,26.51 74.93,27.78 72.39,27.78 71.12,26.51 67.94,26.51 v62.22,32.22
DIN7  (via drill 0.61)
  Top 0.254: v58.41,57.62 63.49,52.54 63.49,44.29 IC5.11 63.49,41.74 64.77,40.48 64.77,32.22 v65.4,31.59 | v73.66,23.96 73.02,24.6 v73.02,29.68
  Bottom 0.254: v58.41,57.62 27.3,57.62 26.03,56.35 IC4.18 | v73.66,23.96 79.37,23.96 82.55,20.79 X1.9 | v73.02,29.68 71.12,31.59 v65.4,31.59
GND  (via drill 0.61)
  Top 0.254: IC10.7 20.95,13.17 22.86,15.08 22.86,29.68 C10.2 22.86,30.95 20.32,33.49 20.32,46.83 IC4.1 | C8.2 72.39,52.54 71.12,51.27 71.12,50.63 IC8.1 | IC4.10 43.17,46.83 41.9,45.55 41.9,37.94 40.63,36.66 IC5.1 | IC12.1 83.18,66.51 83.18,72.86 IC11.10 83.18,74.13 81.91,75.4 81.91,94.45 83.18,95.72 IC11.1 | IC2.7 97.15,48.73 99.06,50.63 99.06,65.24 C2.2 | X1.19 76.83,17.62 78.1,17.62 X1.20 79.37,17.62 81.28,17.62 X1.21 81.91,17.62 83.81,17.62 X1.22 | X1.24 89.53,17.62 87.62,17.62 X1.23 | X1.25 92.07,17.62 90.17,17.62 X1.24 | 90.17,27.14 90.8,27.14 IC13.4 91.44,29.05 91.44,34.12 IC13.13 92.07,34.76 93.34,34.76 IC13.12 94.61,34.76 95.88,34.76 IC13.11 | 90.17,27.14 89.53,27.14 IC13.3 | C13.2 81.91,30.32 81.91,30.95 85.72,34.76 IC13.15 86.36,36.66 83.81,39.2 83.81,42.38 IC12.10 | 90.17,27.14 90.17,18.25 X1.24 | IC7.1 49.52,91.27 50.79,92.54 50.79,93.18 C7.2 | C6.2 15.87,88.73 17.14,87.46 17.14,86.83 IC6.1 | SKT.14 40.63,64.6 41.9,65.88 v41.9,68.41 41.9,83.65 40.63,84.92 IC6.10 | C3.2 70.48,98.89 62.86,98.89 62.86,95.72 61.59,94.45 IC3.2
  Bottom 0.254: C4.2 17.78,50 19.05,48.73 19.68,48.73 IC4.1 | IC9.7 31.75,12.54 30.48,13.81 22.86,13.81 21.59,12.54 IC10.7 | 60.95,51.27 60.95,57.62 IC3.16 | 60.95,51.27 69.21,51.27 IC8.1 | IC5.1 40,34.76 39.36,34.76 35.55,30.95 C9.2 34.92,30.32 29.84,30.32 28.57,31.59 24.76,31.59 23.49,30.32 C10.2 | C5.2 38.09,37.3 39.36,36.03 40,36.03 IC5.1 | 60.95,51.27 60.95,48.09 43.81,48.09 IC4.10 | 95.88,67.14 97.15,67.14 98.42,65.88 C2.2 | 95.88,67.14 94.61,67.14 | 94.61,67.14 88.26,67.14 86.99,68.41 C12.2 85.72,68.41 80.01,68.41 80.01,67.14 81.28,65.88 82.55,65.88 IC12.1 | 94.61,67.14 90.8,70.95 77.47,70.95 IC3.22 | 95.88,67.14 95.88,77.94 IC1.7 | X1.18 73.66,17.62 75.56,17.62 X1.19 | X1.23 86.99,17.62 85.09,17.62 X1.22 | IC13.8 101.59,29.05 96.52,34.12 IC13.11 | 63.49,33.49 63.49,32.22 67.94,27.78 68.58,27.78 IC8.10 71.12,27.78 71.75,28.41 75.56,28.41 76.2,29.05 81.91,29.05 | 63.49,33.49 63.49,34.12 IC5.10 | 81.91,29.05 82.55,28.41 83.18,28.41 IC13.1 | 81.91,29.05 81.28,29.68 C13.2 81.91,30.32 86.36,30.32 88.26,28.41 IC13.3 | IC2.7 95.25,48.09 94.61,47.46 93.34,47.46 92.7,46.83 88.9,46.83 85.09,43.02 IC12.10 | 93.34,97.62 97.15,97.62 98.42,96.35 C1.2 | 93.34,97.62 88.26,97.62 86.99,98.89 C11.2 | C3.2 71.75,98.89 73.02,97.62 81.28,97.62 82.55,96.35 IC11.1 84.45,95.72 87.62,95.72 88.26,95.08 93.34,95.08 93.34,97.62 | IC3.2 59.68,93.81 58.41,95.08 52.7,95.08 51.43,93.81 C7.2 | v41.9,68.41 46.98,68.41 IC7.10 | IC6.1 18.41,86.83 20.32,88.73 40,88.73 40.63,88.1 40.63,87.46 IC6.10 41.27,86.83 42.54,86.83 46.98,91.27 IC7.1 | 63.49,33.49 42.54,33.49 41.27,34.76 IC5.1
  pour Top (isolate 0.305): -0.01,101.43 114.3,101.43 114.3,-0.17 -0.01,-0.17
  pour Bottom (isolate 0.305): -0.01,101.43 114.3,101.43 114.3,-0.17 -0.01,-0.17
LATCH  (via drill 0.61)
  Top 0.254: v39.36,32.86 39.36,50.63 43.17,54.45 IC4.11 | v48.25,31.59 59.68,20.16 v59.68,17.62
  Bottom 0.254: v39.36,32.86 40.63,31.59 v48.25,31.59 | v59.68,17.62 60.95,16.35 68.58,16.35 69.84,17.62 X1.17
LOADGATE\  (via drill 0.61)
  Top 0.254: IC12.19 90.8,63.97 89.53,65.24 89.53,91.91 90.8,93.18 IC11.19 | 38.73,30.32 34.28,34.76 v34.28,46.19 34.28,53.18 33.02,54.45 IC4.15 | 38.73,30.32 38.73,16.98 40,15.71 IC9.9 | 38.73,30.32 41.9,33.49 41.9,36.66 42.54,37.3 42.54,41.11 43.17,41.74 IC5.19 | v24.76,19.52 24.76,10.63 19.05,10.63 17.78,11.9 17.78,22.06 19.68,22.06 IC10.3
  Bottom 0.254: IC9.9 39.36,15.08 35.55,18.89 30.48,18.89 29.21,20.16 IC10.11 27.3,19.52 v24.76,19.52 | v34.28,46.19 43.81,46.19 44.45,46.83 86.36,46.83 86.36,58.26 90.8,62.7 IC12.19
LOADSTROBE\
  Bottom 0.254: IC9.10 40,18.25 36.19,22.06 36.19,27.14 38.73,27.14 39.36,26.51 53.34,26.51 59.68,20.16 60.32,20.16 X1.1
N$1  (via drill 0.61)
  Top 0.254: v29.21,81.11 29.21,77.3 29.84,76.67 29.84,67.78 33.02,64.6 SKT.11
  Bottom 0.254: v29.21,81.11 29.21,88.1 22.22,88.1 20.95,86.83 IC6.2
N$2
  Top 0.254: SKT.12 35.55,64.6 31.75,68.41 31.75,79.84 26.67,84.92 26.67,87.46 26.03,88.1 22.86,88.1 22.86,87.46 IC6.3
N$3  (via drill 0.61)
  Top 0.254: v27.94,65.88 26.67,67.14 26.67,82.38 25.39,83.65 25.39,84.92 IC6.4
  Bottom 0.254: v27.94,65.88 29.21,65.88 29.21,62.06 29.84,61.43 36.19,61.43 37.46,62.7 SKT.13
N$4
  Bottom 0.254: IC6.5 27.94,84.92 27.94,80.48 28.57,80.48 29.21,79.84 29.21,76.67 38.73,76.67 40,77.94 SKT.15
N$5
  Bottom 0.254: SKT.16 38.09,79.84 38.09,84.29 38.73,84.29 39.36,84.92 39.36,88.1 32.38,88.1 31.11,86.83 IC6.6
N$6
  Top 0.254: SKT.17 35.55,79.84 33.02,82.38 33.02,84.92 IC6.7
N$7
  Top 0.254: SKT.18 33.02,79.84 31.75,81.11 31.75,87.46 32.38,88.1 35.55,88.1 35.55,87.46 IC6.8
N$8
  Bottom 0.254: SKT.19 31.11,79.21 37.46,85.56 IC6.9
N$9  (via drill 0.61)
  Top 0.254: v25.39,29.05 24.12,30.32 24.12,76.03 22.86,77.3 SKT.22
  Bottom 0.254: v25.39,29.05 29.21,29.05 32.38,25.87 IC9.2
N$10
  Top 0.254: IC9.1 32.38,28.41 30.48,30.32 30.48,45.55 29.21,46.83 29.21,76.03 27.94,77.3 SKT.20
N$11  (via drill 0.61)
  Top 0.254: 24.76,4.92 24.12,4.92 | 24.76,4.92 104.14,4.92 104.14,21.43 100.33,25.23 100.33,29.05 v99.06,30.32 | SKT.26 12.69,77.3 13.96,76.03 13.96,22.7 12.06,20.79 12.06,14.44 22.86,3.65 24.76,3.65 24.76,4.92
  Bottom 0.254: v99.06,30.32 96.52,32.86 78.73,32.86 IC8.13
N$12  (via drill 0.61)
  Top 0.254: v67.94,12.54 69.21,13.81 69.21,18.25 70.48,19.52 70.48,25.87 71.75,27.14 71.75,30.95 76.2,35.4 IC8.14 | 10.15,62.06 SKT.2 10.15,62.06 | 10.15,62.06 10.79,62.06 v10.79,15.71
  Bottom 0.254: v67.94,12.54 66.67,11.27 19.05,11.27 15.23,11.27 v10.79,15.71
N$13  (via drill 0.61)
  Top 0.254: v31.75,31.59 34.92,28.41 34.92,19.52 34.28,18.89 31.11,18.89 31.11,14.44 31.75,13.81 34.28,13.81 37.46,10.63 74.93,10.63 74.93,18.25 76.2,19.52 76.2,26.51 75.56,27.14 75.56,33.49 76.2,34.12 79.37,34.12 79.37,36.03 78.1,37.3 IC8.15
  Bottom 0.254: v31.75,31.59 22.22,41.11 11.42,41.11 11.42,68.41 20.32,77.3 SKT.23
N$14  (via drill 0.61)
  Top 0.254: v97.79,37.3 97.79,6.18 31.75,6.18 26.03,11.9 26.03,28.41 26.67,29.05 26.67,64.6 26.03,65.24 26.03,76.67 25.39,77.3 SKT.21
  Bottom 0.254: v97.79,37.3 94.61,40.48 78.73,40.48 IC8.16
N$15  (via drill 0.61)
  Top 0.254: v80.01,41.74 78.73,43.02 IC8.17 | SKT.24 17.78,77.3 16.51,76.03 16.51,57.62 15.87,56.98 15.87,23.33 17.14,22.06 17.14,11.27 22.22,6.18 v24.12,6.18
  Bottom 0.254: v24.12,6.18 99.69,6.18 107.95,14.44 107.95,41.74 v80.01,41.74
N$16  (via drill 0.61)
  Top 0.254: v69.21,96.35 v69.21,53.18 | v78.1,56.98 79.37,55.72 79.37,47.46 78.1,46.19 IC8.18
  Bottom 0.254: v69.21,96.35 67.31,98.26 21.59,98.26 21.59,92.54 16.51,87.46 15.23,87.46 15.23,79.84 SKT.25 | v69.21,53.18 66.67,53.18 65.4,54.45 67.94,56.98 v78.1,56.98
N$17
  Bottom 0.254: SKT.3 13.33,63.97 25.39,76.03 40.63,76.03 46.35,81.75 46.35,87.46 49.52,87.46 50.79,86.19 54.6,86.19 IC7.18
N$18  (via drill 0.61)
  Top 0.254: v46.35,74.77 50.79,74.77 v50.79,83.65
  Bottom 0.254: v46.35,74.77 26.67,74.77 15.87,63.97 SKT.4 | v50.79,83.65 54.6,83.65 IC7.17
N$19  (via drill 0.61)
  Top 0.254: v46.35,72.22 52.06,72.22 v52.06,81.11
  Bottom 0.254: v46.35,72.22 26.67,72.22 18.41,63.97 SKT.5 | v52.06,81.11 54.6,81.11 IC7.16
N$20  (via drill 0.61)
  Top 0.254: v53.34,51.27 53.34,65.88 53.97,66.51 53.97,76.67 55.24,77.94 IC7.15
  Bottom 0.254: v53.34,51.27 24.12,51.27 24.12,56.98 23.49,57.62 19.68,57.62 19.68,61.43 20.32,62.06 SKT.6
N$21  (via drill 0.61)
  Top 0.254: v22.86,72.22 22.86,64.6 SKT.7
  Bottom 0.254: v22.86,72.22 26.03,75.4 45.08,75.4 46.98,77.3 49.52,77.3 50.79,76.03 54.6,76.03 IC7.14
N$22  (via drill 0.61)
  Top 0.254: v57.78,58.89 57.78,71.59 56.51,72.86 IC7.13
  Bottom 0.254: v57.78,58.89 57.14,58.26 20.32,58.26 20.32,60.8 21.59,62.06 22.22,61.43 23.49,61.43 24.76,62.7 SKT.8
N$23  (via drill 0.61)
  Top 0.254: v50.16,67.14 50.79,67.78 v50.79,70.95
  Bottom 0.254: v50.16,67.14 26.67,67.14 26.67,65.88 27.94,64.6 SKT.9 | v50.79,70.95 54.6,70.95 IC7.12
N$24
  Bottom 0.254: SKT.10 31.11,63.97 33.02,65.88 52.06,65.88 54.6,68.41 IC7.11
N$25
  Top 0.254: IC9.4 32.38,20.79 32.38,22.06 IC9.3
READ\
  Bottom 0.254: IC9.6 31.75,15.08 30.48,16.35 26.67,16.35 22.22,20.79 22.22,29.05 8.88,42.38 8.88,91.91 18.41,91.91 19.68,93.18 IC6.19
RESET
  Top 0.254: IC10.5 20.32,18.25 20.32,19.52 IC10.4
  Bottom 0.254: JP1.1 16.51,20.16 19.05,20.16 IC10.4
RESET\
  Bottom 0.254: IC10.6 19.05,15.08 16.51,15.08 JP1.3
RUN\  (via drill 0.61)
  Top 0.254: IC3.24 75.56,75.4 74.29,74.13 74.29,62.7 74.93,62.06 74.29,61.43 74.29,57.62 76.2,55.72 76.2,51.91 75.56,51.27 75.56,50 76.83,48.73 IC8.19 76.83,47.46 74.93,45.55 74.93,37.3 v75.56,36.66 | v58.41,76.03 57.78,76.67 57.78,86.83 56.51,88.1 IC7.19 | v67.94,36.66 67.94,19.52 66.67,18.25 66.67,11.27 38.09,11.27 34.92,14.44 34.92,15.71 33.65,16.98 IC9.5
  Bottom 0.254: IC10.10 29.21,17.62 31.75,17.62 IC9.5 | v58.41,76.03 59.68,74.77 62.22,74.77 63.49,76.03 74.93,76.03 IC3.24 | v67.94,36.66 v75.56,36.66
SELA  (via drill 0.61)
  Top 0.254: v21.59,39.84 21.59,53.18 22.86,54.45 IC4.19 | v29.21,32.22 29.84,31.59 29.84,13.17 33.65,9.36 85.72,9.36 85.72,18.25 86.99,19.52 86.99,25.87 87.62,26.51 87.62,32.86 88.9,34.12 IC13.14
  Bottom 0.254: v29.21,32.22 v21.59,39.84
SELB  (via drill 0.61)
  Top 0.254: v37.46,25.87 37.46,30.32 31.75,36.03 31.75,53.18 30.48,54.45 IC4.16 | v85.72,23.96 86.36,24.6 86.36,26.51 IC13.2
  Bottom 0.254: v37.46,25.87 39.36,23.96 54.6,23.96 59.68,18.89 83.81,18.89 84.45,19.52 84.45,23.96 v85.72,23.96
VCC  (via drill 0.61)
  Top 0.508: IC6.20 17.14,93.81 15.87,93.81 C6.1 | IC10.14 27.94,28.41 27.94,29.68 C10.1 27.94,30.95 v27.94,42.38 | IC9.14 40.63,28.41 40.63,29.68 C9.1 | 19.05,55.72 19.68,55.72 IC4.20 | 19.05,55.72 18.41,55.72 C4.1 | 19.05,55.72 19.05,91.27 17.78,92.54 IC6.20 | IC7.20 55.88,91.91 55.88,93.18 C7.1 55.88,94.45 55.88,97.62 21.59,97.62 18.41,94.45 IC6.20 | IC3.30 76.83,91.91 78.1,93.18 78.1,94.45 76.83,95.72 IC3.32 76.2,96.99 76.2,98.26 C3.1 | IC13.16 83.18,35.4 81.91,35.4 C13.1 81.28,36.03 v81.28,50 v81.28,67.14 | IC8.20 77.47,51.27 77.47,52.54 C8.1 | IC12.20 91.44,66.51 91.44,67.78 C12.1 | IC2.14 104.14,63.97 104.14,65.24 C2.1 | IC11.20 91.44,96.99 91.44,98.26 C11.1 92.07,98.89 104.14,98.89 104.14,96.99 C1.1 104.14,95.72 104.14,94.45 IC1.14
  Bottom 0.508: SKT.28 7.62,79.84 7.62,93.81 14.6,93.81 C6.1 | C10.1 28.57,30.32 29.21,29.68 34.28,29.68 36.19,27.78 39.36,27.78 IC9.14 | IC5.20 40,43.02 38.73,43.02 C5.1 38.09,43.65 31.75,43.65 | 31.75,43.65 31.75,49.37 31.11,50 20.32,50 20.32,54.45 IC4.20 | v27.94,42.38 29.21,43.65 31.75,43.65 | IC7.20 57.14,91.27 58.41,92.54 73.66,92.54 74.93,91.27 IC3.30 | v81.28,50 80.64,50.63 78.73,50.63 IC8.20 | IC2.14 102.87,63.34 101.59,62.06 95.25,62.06 92.07,65.24 IC12.20 90.17,65.88 88.26,65.88 86.99,67.14 v81.28,67.14 | C2.1 104.14,66.51 104.14,77.3 106.04,77.3 108.58,79.84 108.58,93.18 104.77,93.18 IC1.14 | C3.1 76.83,98.89 77.47,98.26 85.09,98.26 86.99,96.35 90.17,96.35 IC11.20
WE\  (via drill 0.61)
  Top 0.254: v106.04,19.52 107.31,20.79 v107.31,90.64 | v80.01,95.08 78.73,93.81 78.73,91.27 76.83,89.37 IC3.29
  Bottom 0.254: v106.04,19.52 100.33,13.81 43.17,13.81 41.9,12.54 IC9.8 | v107.31,90.64 105.41,92.54 89.53,92.54 86.99,95.08 v80.01,95.08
